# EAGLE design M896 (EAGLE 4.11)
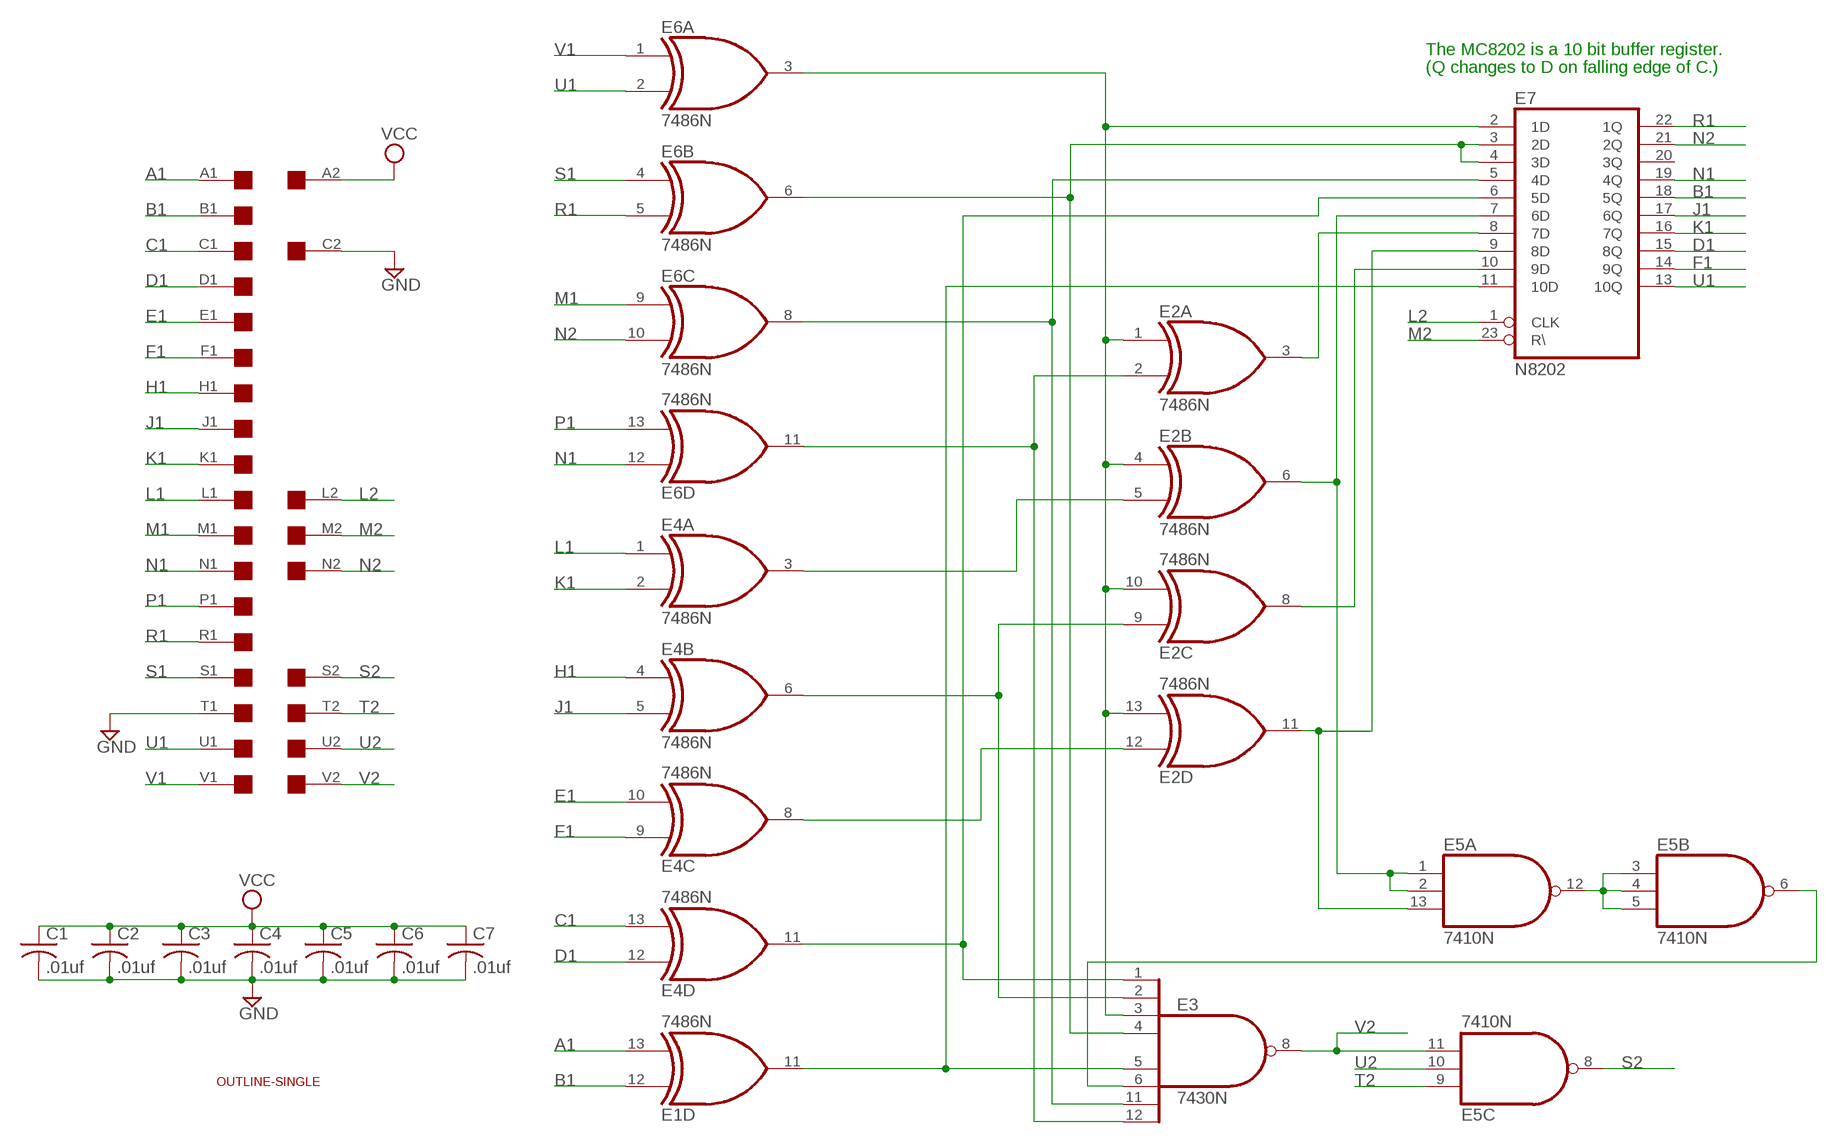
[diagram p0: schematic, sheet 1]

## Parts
C1  .01uf  C-US050-025X075  [C050-025X075]
C2  .01uf  C-US050-025X075  [C050-025X075]
C3  .01uf  C-US050-025X075  [C050-025X075]
C4  .01uf  C-US050-025X075  [C050-025X075]
C5  .01uf  C-US050-025X075  [C050-025X075]
C6  .01uf  C-US050-025X075  [C050-025X075]
C7  .01uf  C-US050-025X075  [C050-025X075]
E1  7486N  [DIL14]
E2  7486N  [DIL14]
E3  7430N  [DIL14]
E4  7486N  [DIL14]
E5  7410N  [DIL14]
E6  7486N  [DIL14]
E7  N8202  [DIL24]
U$1  EDGE-2CONNECTOR  [EDGE-CON2]
U$4  OUTLINE-SINGLE  [SINGLE]

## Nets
A1: E1.13(D:I1) U$1.A1
B1: E1.12(D:I0) E7.18(5Q) U$1.B1
C1: E4.13(D:I1) U$1.C1
D1: E4.12(D:I0) E7.15(8Q) U$1.D1
E1: E4.10(C:I1) U$1.E1
F1: E4.9(C:I0) E7.14(9Q) U$1.F1
GND [power]: C1.2 C2.2 C3.2 C4.2 C5.2 C6.2 C7.2 U$1.C2 U$1.T1
H1: E4.4(B:I0) U$1.H1
J1: E4.5(B:I1) E7.17(6Q) U$1.J1
K1: E4.2(A:I1) E7.16(7Q) U$1.K1
L1: E4.1(A:I0) U$1.L1
L2: E7.1(CLK) U$1.L2
M1: E6.9(C:I0) U$1.M1
M2: E7.23(R\) U$1.M2
N1: E6.12(D:I0) E7.19(4Q) U$1.N1
N2: E6.10(C:I1) E7.21(2Q) U$1.N2
N$1: E2.1(A:I0) E2.4(B:I0) E2.10(C:I1) E2.13(D:I1) E3.3(I2) E6.3(A:O) E7.2(1D)
N$2: E2.2(A:I1) E3.12(I7) E6.11(D:O)
N$3: E2.5(B:I1) E4.3(A:O)
N$4: E2.9(C:I0) E3.2(I1) E4.6(B:O)
N$5: E2.12(D:I0) E4.8(C:O)
N$6: E1.11(D:O) E3.5(I4) E7.11(10D)
N$7: E3.1(I0) E4.11(D:O) E7.6(5D)
N$8: E5.3(B:I0) E5.4(B:I1) E5.5(B:I2) E5.12(A:O)
N$9: E3.11(I6) E6.8(C:O) E7.5(4D)
N$10: E3.4(I3) E6.6(B:O) E7.3(2D) E7.4(3D)
N$11: E3.6(I5) E5.6(B:O)
N$12: E2.6(B:O) E5.1(A:I0) E5.2(A:I1) E7.7(6D)
N$13: E2.11(D:O) E5.13(A:I2) E7.9(8D)
N$14: E2.3(A:O) E7.8(7D)
N$15: E2.8(C:O) E7.10(9D)
P1: E6.13(D:I1) U$1.P1
R1: E6.5(B:I1) E7.22(1Q) U$1.R1
S1: E6.4(B:I0) U$1.S1
S2: E5.8(C:O) U$1.S2
T2: E5.9(C:I0) U$1.T2
U1: E6.2(A:I1) E7.13(10Q) U$1.U1
U2: E5.10(C:I1) U$1.U2
V1: E6.1(A:I0) U$1.V1
V2: E3.8(O) E5.11(C:I2) U$1.V2
VCC [power]: C1.1 C2.1 C3.1 C4.1 C5.1 C6.1 C7.1 U$1.A2
Unconnected: E1.1(A:I0) E1.2(A:I1) E1.3(A:O) E1.4(B:I0) E1.5(B:I1) E1.6(B:O) E1.8(C:O) E1.9(C:I0) E1.10(C:I1) E7.20(3Q) U$1.B2 U$1.D2 U$1.E2 U$1.F2 U$1.H2 U$1.J2 U$1.K2 U$1.P2 U$1.R2

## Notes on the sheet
- The MC8202 is a 10 bit buffer register.
- (Q changes to D on falling edge of C.)

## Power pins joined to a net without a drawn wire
GND: E1.7(P:GND) E2.7(P:GND) E3.7(GND) E4.7(P:GND) E5.7(P:GND) E6.7(P:GND) E7.12(GND)
VCC: E1.14(P:VCC) E2.14(P:VCC) E3.14(VCC) E4.14(P:VCC) E5.14(P:VCC) E6.14(P:VCC) E7.24(VCC)

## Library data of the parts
C1-C7 = rcl:C-US: CAPACITOR, American symbol
E1 E2 E4 E6 = 74xx-jameco:74*86: Quad 2-input EXCLUSIV-OR (XOR) gate
E3 = 74xx-jameco:74*30: 8-input NAND gate
E5 = 74xx-jameco:74*10: Triple 3-input NAND gate
E7 = dec-con:N8202: 10 bit register
U$1 = dec-con:EDGE-2: Double-Sided DEC edge connector.
U$4 = dec-con:OUTLINE-*: Board outlines for DEC boards.

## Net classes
1 power: width 0.508 mm

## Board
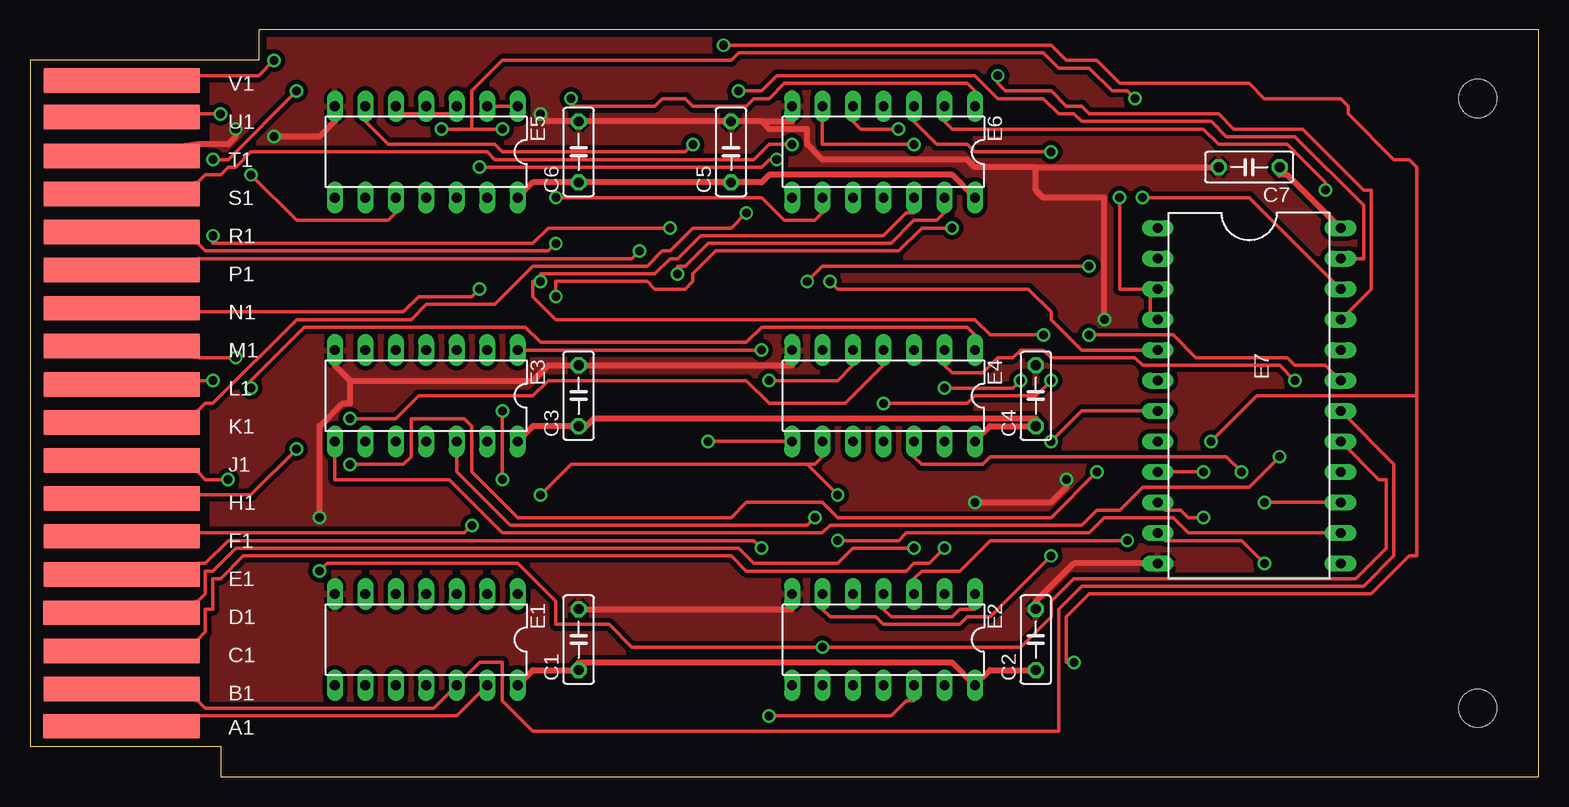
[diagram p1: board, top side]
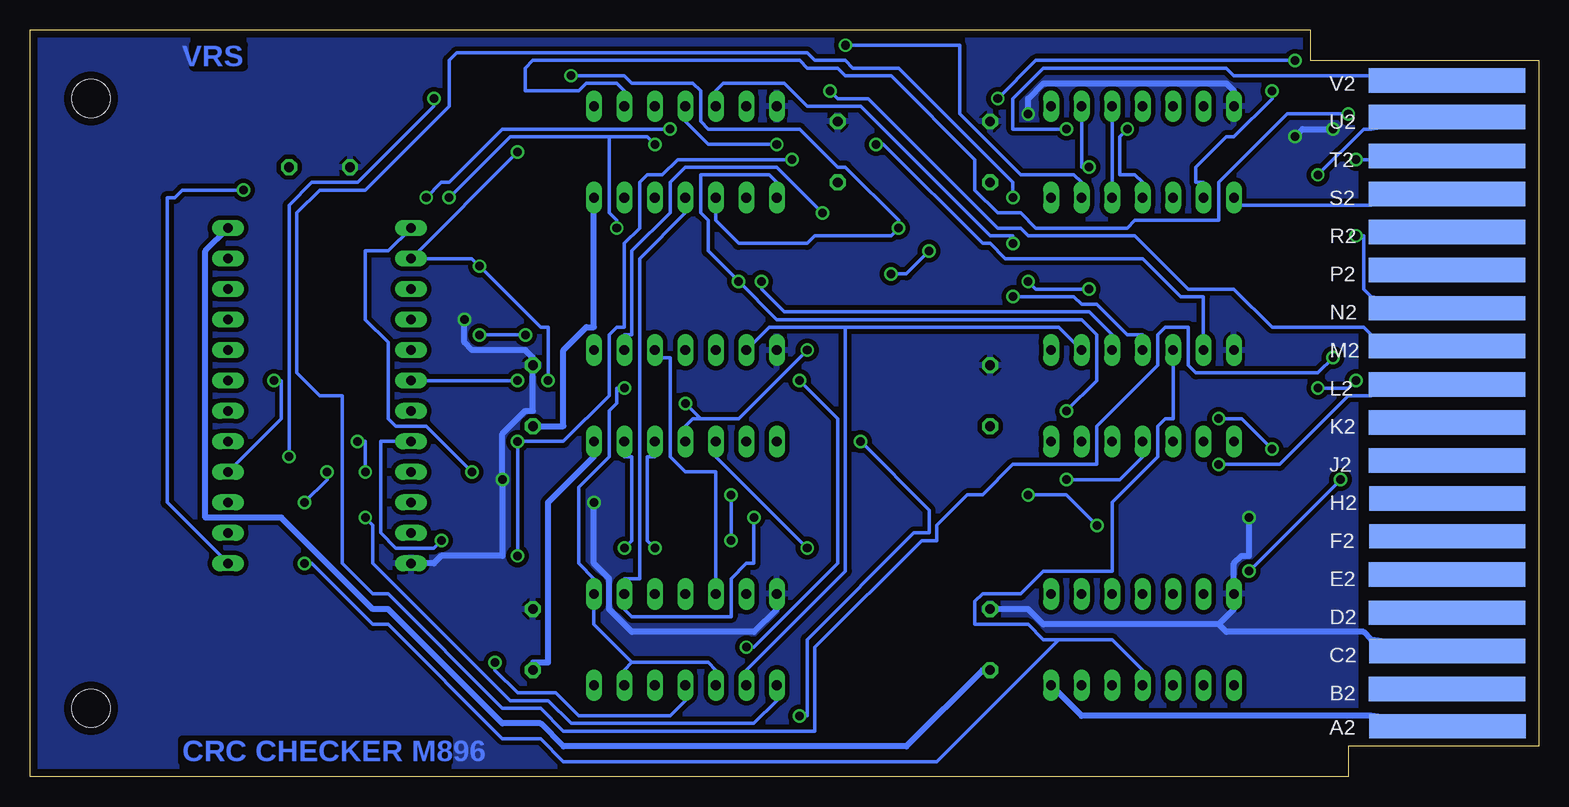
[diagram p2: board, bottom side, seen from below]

Size 125.73 x 62.23 mm. Coordinates in mm from the lower left corner, seen from the top.
Copper layers (1*16): Top 0.035mm / dielectric 1.5mm / Bottom 0.035mm
Design rules "10mils": minimum track width 12mil, minimum drill 28mil, track to track 10mil, track to pad 10mil, pad to pad 10mil, via to via 10mil, smd to smd 10mil, copper to edge 25mil, drill to drill 10mil, minimum pad ring 10mil, minimum via ring 8mil, stop-mask expansion 0mil, vias tented up to drill 0mil, thermal gap 10mil

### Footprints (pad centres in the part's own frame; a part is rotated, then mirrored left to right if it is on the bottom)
C050-025X075 = drill 0.813 octagon: 1 -2.54,0; 2 2.54,0
DIL14 = drill 0.813 long: 1 -7.62,-3.81; 2 -5.08,-3.81; 3 -2.54,-3.81; 4 0,-3.81; 5 2.54,-3.81; 6 5.08,-3.81; 7 7.62,-3.81; 8 7.62,3.81; 9 5.08,3.81; 10 2.54,3.81; 11 0,3.81; 12 -2.54,3.81; 13 -5.08,3.81; 14 -7.62,3.81
DIL24 = drill 0.813 long: 1 -12.7,-7.62; 2 -10.16,-7.62; 3 -7.62,-7.62; 4 -5.08,-7.62; 5 -2.54,-7.62; 6 0,-7.62; 7 2.54,-7.62; 8 5.08,-7.62; 9 7.62,-7.62; 10 10.16,-7.62; 11 12.7,-7.62; 12 15.24,-7.62; 13 15.24,7.62; 14 12.7,7.62; 15 10.16,7.62; 16 7.62,7.62; 17 5.08,7.62; 18 2.54,7.62; 19 0,7.62; 20 -2.54,7.62; 21 -5.08,7.62; 22 -7.62,7.62; 23 -10.16,7.62; 24 -12.7,7.62
EDGE-CON2 = smd 13.017 x 2.032: A1 7.633,4.207; B1 7.639,7.327; C1 7.636,10.489; D1 7.633,13.665; E1 7.642,16.84; F1 7.642,20.041; H1 7.642,23.19; J1 7.642,26.34; K1 7.642,29.515; L1 7.642,32.69; M1 7.642,35.89; N1 7.642,39.04; P1 7.642,42.24; R1 7.642,45.39; S1 7.642,48.565; T1 7.642,51.74; U1 7.642,54.966; V1 7.642,58.026 | smd 13.017 x 2.032 bottom: A2 7.614,4.207; B2 7.642,7.328; C2 7.617,10.49; D2 7.642,13.665; E2 7.642,16.84; F2 7.617,20.041; H2 7.617,23.19; J2 7.642,26.34; K2 7.642,29.515; L2 7.642,32.69; M2 7.642,35.89; N2 7.642,39.04; P2 7.642,42.24; R2 7.642,45.39; S2 7.642,48.565; T2 7.642,51.74; U2 7.642,54.966; V2 7.642,58.026
SINGLE = hole 3.175: 120.65,56.515; 120.65,5.715

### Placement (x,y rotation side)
C1  45.72,11.43 90 top
C2  83.82,11.43 90 top
C3  45.72,31.75 90 top
C4  83.82,31.75 90 top
C5  58.42,52.07 90 top
C6  45.72,52.07 90 top
C7  101.6,50.8 180 top
E1  33.02,11.43 180 top
E2  71.12,11.43 180 top
E3  33.02,31.75 180 top
E4  71.12,31.75 180 top
E5  33.02,52.07 180 top
E6  71.12,52.07 180 top
E7  101.6,33.02 270 top
U$1  0,0 0 top
U$4  0,0 0 top

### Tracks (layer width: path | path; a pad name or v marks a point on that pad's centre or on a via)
A1
  Top 0.305: E1.13 35.56,5.08 13.97,5.08 U$1.A1
B1
  Top 0.305: U$1.B1 13.97,6.35 14.61,5.71 33.66,5.71 E1.12 37.47,9.53 39.37,9.53 39.37,6.35 41.91,3.81 85.73,3.81 85.73,13.97 87.63,15.88 111.13,15.88 113.67,18.41 113.67,26.04 E7.18
C1  (via drill 0.71)
  Top 0.305: v76.2,19.05 74.93,17.78 73.66,17.78 73.03,17.14 59.69,17.14 58.42,18.41 17.78,18.41 15.88,16.51 15.24,16.51 15.24,13.97 14.61,13.97 14.61,12.06 13.97,11.43 U$1.C1
  Bottom 0.305: v76.2,19.05 75.57,19.68 75.57,26.67 76.2,26.67 E4.13
D1  (via drill 0.71)
  Top 0.305: v73.66,19.05 68.58,19.05 67.31,17.78 60.33,17.78 59.06,19.05 17.15,19.05 15.24,17.14 14.61,17.14 14.61,15.24 13.97,14.61 U$1.D1 | v100.97,25.4 99.7,26.67 80.01,26.67 79.38,26.04 74.3,26.04 73.66,26.67 E4.12 | v102.87,22.86 E7.15
  Bottom 0.305: v73.66,19.05 74.3,19.68 74.3,26.67 73.66,26.67 E4.12 | v102.87,22.86 100.97,24.77 v100.97,25.4
E1  (via drill 0.71)
  Top 0.305: v60.96,19.05 60.33,19.68 16.51,19.68 14.61,17.78 13.97,17.78 U$1.E1
  Bottom 0.305: v60.96,19.05 68.58,26.67 E4.10
F1  (via drill 0.71)
  Top 0.305: v36.83,20.95 36.2,20.32 13.97,20.32 U$1.F1 | v42.55,23.5 45.09,26.04 64.77,26.04 | 64.77,26.04 65.41,26.04 66.04,26.67 E4.9 | v67.31,19.68 72.39,19.68 73.03,20.32 88.27,20.32 89.54,21.59 95.25,21.59 96.52,20.32 E7.14 | 64.77,26.04 v67.31,23.5
  Bottom 0.305: v36.83,20.95 39.37,23.5 v42.55,23.5 | v67.31,23.5 v67.31,19.68
GND  (via drill 0.71)
  Top 0.508: E4.7 63.5,34.29 C3.2 43.18,34.29 41.91,33.02 26.67,33.02 | 26.67,33.02 25.4,34.29 E3.7 | E2.7 63.5,13.97 C1.2 | 26.67,33.02 26.67,31.11 26.04,31.11 24.13,29.21 v24.13,21.59 | v17.15,53.98 17.15,53.34 16.51,52.7 13.97,52.7 U$1.T1 | v20.32,53.34 24.13,53.34 25.4,54.61 E5.7 | C2.2 83.82,14.61 87,17.78 E7.12 | 60.96,54.61 63.5,54.61 E6.7 | 60.96,54.61 C5.2 C6.2 43.18,54.61 v42.55,55.24 | 83.82,50.8 78.74,50.8 78.11,51.44 66.04,51.44 64.77,52.7 64.77,53.98 61.6,53.98 60.96,54.61 | 83.82,50.8 C7.2 | v89.54,38.1 89.54,48.26 84.46,48.26 83.82,48.9 83.82,50.8 | v78.74,22.86 85.09,22.86 86.36,24.13 v86.36,24.77
  Bottom 0.508: 26.67,12.7 25.4,13.97 E1.7 25.4,17.78 24.77,18.41 24.13,18.41 v24.13,21.59 | 26.67,12.7 41.28,12.7 42.55,13.97 C1.2 | 26.67,12.7 26.04,12.06 14.61,12.06 13.97,11.43 U$1.C2 | v17.15,53.98 19.69,53.98 v20.32,53.34 | E7.12 92.08,17.78 91.44,18.41 86.36,18.41 v86.36,24.77 86.36,28.57 84.46,30.48 83.82,30.48 C4.2 83.82,34.92 84.46,35.56 88.9,35.56 89.54,36.2 v89.54,38.1 | v42.55,55.24 42.55,56.52 41.28,57.78 26.04,57.78 25.4,57.15 E5.7 | v78.74,22.86 78.74,17.78 77.47,16.51 77.47,13.97 75.57,12.06 65.41,12.06 63.5,13.97 E2.7
  pour Top (isolate 0.381): 15.24,62.23 125.73,62.23 125.73,0 15.24,0
  pour Bottom (isolate 0.381): 15.24,62.23 125.73,62.23 125.73,0 15.24,0
H1  (via drill 0.71)
  Top 0.305: v22.23,27.3 18.42,23.5 13.97,23.5 U$1.H1 | v26.67,29.84 30.48,29.84 32.39,31.75 41.91,31.75 43.18,33.02 59.69,33.02 61.6,31.11 67.95,31.11 71.12,34.29 E4.4
  Bottom 0.305: v22.23,27.3 24.77,29.84 v26.67,29.84
J1  (via drill 0.71)
  Top 0.305: v16.51,24.77 14.61,24.77 13.97,25.4 U$1.J1 | v24.13,17.14 24.77,17.78 40.64,17.78 43.82,14.61 43.82,12.7 48.26,12.7 50.17,10.79 v66.04,10.79 82.55,10.79 85.09,13.34 85.09,14.61 87,16.51 110.49,16.51 113.03,19.05 113.03,24.77 112.4,24.77 E7.17 | v61.6,33.02 67.31,33.02 68.58,34.29 E4.5
  Bottom 0.305: v16.51,24.77 v24.13,17.14 | v61.6,33.02 58.42,29.84 58.42,17.78 65.41,10.79 v66.04,10.79
K1  (via drill 0.71)
  Top 0.305: v59.69,46.99 58.42,45.72 55.25,45.72 53.34,43.81 52.71,43.81 51.44,42.55 41.91,42.55 38.74,39.37 33.02,39.37 31.75,38.1 22.23,38.1 15.24,31.11 14.61,31.11 13.97,30.48 U$1.K1 | v105.41,33.02 104.14,34.29 92.71,34.29 92.08,34.92 85.09,34.92 84.46,35.56 82.55,35.56 81.92,34.92 80.65,34.92 79.38,33.66 76.84,33.66 76.2,34.29 E4.2
  Bottom 0.305: v59.69,46.99 63.5,50.8 71.12,50.8 72.39,49.53 72.39,46.99 75.57,43.81 75.57,36.83 76.2,36.83 E4.2 | v105.41,33.02 104.78,33.02 104.78,29.84 E7.16
L1  (via drill 0.71)
  Top 0.305: v15.24,33.02 13.97,33.02 U$1.L1 | v18.42,32.38 18.42,33.02 22.86,37.47 41.28,37.47 42.55,36.2 59.69,36.2 60.96,37.47 78.11,37.47 78.74,36.83 E4.1
  Bottom 0.305: v15.24,33.02 15.88,32.38 v18.42,32.38
L2  (via drill 0.71)
  Top 0.305: v26.67,26.04 31.12,26.04 31.75,26.67 31.75,29.84 36.2,29.84 36.83,29.21 36.83,25.4 40.64,21.59 58.42,21.59 59.69,22.86 66.04,22.86 67.31,21.59 85.09,21.59 v88.9,25.4
  Bottom 0.305: v26.67,26.04 21.59,26.04 15.88,31.75 13.97,31.75 U$1.L2 | v88.9,25.4 92.71,29.21 95.25,29.21 95.89,29.84 95.89,36.2 97.79,38.1 97.79,43.81 95.89,43.81 E7.1
M1  (via drill 0.71)
  Top 0.305: v17.15,34.92 13.97,34.92 U$1.M1 | v43.82,48.26 60.96,48.26 62.87,46.35 65.41,46.35 66.04,46.99 E6.9
  Bottom 0.305: v17.15,34.92 18.42,33.66 28.58,33.66 29.21,34.29 29.21,37.47 31.12,37.47 31.75,36.83 31.75,34.29 36.83,29.21 36.83,26.04 43.82,26.04 46.36,23.5 47.63,23.5 50.17,20.95 50.17,19.68 51.44,19.68 60.33,10.79 60.33,3.81 81.28,3.81 83.19,5.71 86.36,5.71 95.89,15.24 97.16,15.24 99.7,17.78 99.7,31.75 101.6,31.75 103.51,33.66 103.51,46.99 101.6,48.9 97.79,48.9 90.81,55.88 90.81,59.69 90.17,60.33 60.96,60.33 60.33,59.69 57.79,59.69 57.15,59.05 53.34,59.05 43.82,49.53 v43.82,48.26
M2  (via drill 0.71)
  Top 0.305: v59.06,57.15 60.96,57.15 62.23,58.42 78.74,58.42 80.65,56.52 84.46,56.52 85.73,55.24 87,55.24 87.63,54.61 98.43,54.61 99.7,53.34 105.41,53.34 111.13,47.62 111.13,43.18 E7.23
  Bottom 0.305: v59.06,57.15 58.42,56.52 55.88,56.52 45.09,45.72 43.18,45.72 42.55,45.09 33.66,45.09 29.21,40.64 25.4,40.64 22.23,37.47 14.61,37.47 13.97,36.83 U$1.M2
N1  (via drill 0.71)
  Top 0.305: v37.47,40.64 36.83,40.01 32.39,40.01 31.12,38.73 13.97,38.73 U$1.N1 | E6.12 73.66,46.99 73.03,46.99 71.12,45.09 55.88,45.09 53.98,43.18 53.34,43.18 52.07,41.91 42.55,41.91 v42.55,41.27 41.91,41.27 41.91,40.01 43.82,38.1 78.74,38.1 80.01,36.83 v84.46,36.83 | v88.27,36.83 95.25,36.83 97.16,34.92 104.78,34.92 105.41,34.29 107.95,34.29 E7.19
  Bottom 0.305: v37.47,40.64 41.91,40.64 v42.55,41.27 | v84.46,36.83 v88.27,36.83
N2  (via drill 0.71)
  Top 0.305: v15.24,45.09 15.24,44.45 41.91,44.45 43.18,45.72 v53.34,45.72 | v80.65,58.42 80.65,57.78 81.28,57.15 85.09,57.15 86.36,55.88 87.63,55.88 88.27,55.24 99.06,55.24 100.33,53.98 106.05,53.98 111.13,48.9 111.76,48.9 111.76,40.64 E7.21
  Bottom 0.305: v15.24,45.09 14.61,45.09 14.61,40.64 13.97,40.01 U$1.N2 | E6.10 68.58,46.35 66.68,44.45 60.96,44.45 60.33,45.09 53.98,45.09 v53.34,45.72 53.34,46.35 57.79,50.8 58.42,50.8 61.6,53.98 69.22,53.98 69.85,54.61 69.85,57.15 70.49,57.78 75.57,57.78 76.2,58.42 v80.65,58.42
N$1  (via drill 0.71)
  Top 0.305: E2.4 71.12,13.97 71.76,13.34 76.84,13.34 77.47,13.97 78.74,13.97 E2.1 | v85.09,52.07 78.74,52.07 78.11,52.7 75.57,52.7 73.66,54.61 E6.3 | v64.77,41.27 66.04,42.55 v88.27,42.55 | v76.2,32.38 81.92,32.38 v82.55,33.02
  Bottom 0.305: 75.57,9.53 69.22,9.53 68.58,8.89 E2.10 | 75.57,9.53 76.2,8.89 E2.13 | 75.57,9.53 78.74,12.7 E2.1 78.74,16.51 80.01,17.78 80.01,24.13 77.47,26.67 77.47,30.48 76.84,31.11 76.84,32.38 v76.2,32.38 | v85.09,52.07 E7.2 88.9,43.18 v88.27,42.55 83.19,37.47 82.55,37.47 v82.55,33.02 | v64.77,41.27 64.77,40.64 62.87,38.73 37.47,38.73 35.56,36.83 E3.3
N$2  (via drill 0.71)
  Top 0.305: v65.41,21.59 64.77,20.95 40.01,20.95 35.56,25.4 E3.12
  Bottom 0.305: E6.11 71.12,46.99 74.93,43.18 74.93,16.51 76.2,16.51 E2.2 76.2,13.97 75.57,13.34 67.31,13.34 67.31,16.51 66.04,17.78 65.41,17.78 v65.41,21.59
N$3
  Bottom 0.305: E2.5 68.58,25.4 71.12,25.4 72.39,26.67 72.39,34.92 73.03,34.92 E4.3
N$4
  Bottom 0.305: 57.79,37.47 57.79,17.14 66.04,8.89 E2.9 | 57.79,37.47 64.14,37.47 E4.6 | 57.79,37.47 40.01,37.47 E3.2
N$5  (via drill 0.71)
  Top 0.305: v61.6,5.08 71.76,5.08 73.03,6.35 73.66,6.35 E2.12 | v56.52,27.94 E4.8
  Bottom 0.305: v56.52,27.94 50.8,22.23 50.8,20.32 52.07,20.32 60.96,11.43 60.96,5.08 v61.6,5.08
N$6  (via drill 0.71)
  Top 0.305: v102.87,17.78 100.97,19.68 94.62,19.68 E7.11
  Bottom 0.305: 40.01,11.43 35.56,11.43 33.02,8.89 E1.11 | 40.01,11.43 41.28,11.43 42.55,12.7 46.99,12.7 46.99,14.61 46.36,15.24 43.18,15.24 41.28,17.14 35.56,17.14 35.56,22.86 31.75,26.67 31.75,29.21 31.12,29.84 30.48,29.84 E3.5 | v102.87,17.78 102.24,17.78 97.16,12.7 95.89,12.7 86.36,3.17 83.19,3.17 81.28,1.27 50.17,1.27 40.01,11.43
N$7  (via drill 0.71)
  Top 0.305: E3.1 v60.96,35.56 | v85.09,33.02 83.82,31.75 78.74,31.75 78.11,31.11 v71.12,31.11
  Bottom 0.305: v60.96,35.56 66.68,29.84 69.85,29.84 | 69.85,29.84 70.49,29.84 71.12,29.21 E4.11 | 69.85,29.84 v71.12,31.11 | v85.09,33.02 E7.6
N$8
  Top 0.305: E5.5 31.12,55.24 32.39,55.24 E5.4 33.66,55.24 34.93,55.24 E5.3
  Bottom 0.305: E5.12 E5.3
N$9  (via drill 0.71)
  Top 0.305: v39.37,24.77 v39.37,30.48 | v66.68,41.27 67.31,40.64 83.19,40.64 85.09,38.73 85.09,38.1 87.63,35.56 E7.5
  Bottom 0.305: v39.37,24.77 34.93,24.77 33.02,26.67 E3.11 | v39.37,30.48 36.83,33.02 36.83,36.83 38.1,38.1 63.5,38.1 v66.68,41.27 69.22,43.81 69.22,46.35 69.85,46.99 69.85,50.16 64.14,50.16 63.5,49.53 E6.8
N$10  (via drill 0.71)
  Top 0.305: v73.66,52.7 66.04,52.7 E6.6 | v90.81,48.26 90.81,40.64 E7.3 93.35,40.01 93.35,38.73 E7.4 | v43.82,40.01 43.82,41.27 51.44,41.27 52.07,40.64 54.61,40.64 55.25,41.27 55.25,41.91 57.15,43.81 72.39,43.81 74.3,45.72 v76.84,45.72
  Bottom 0.305: v73.66,52.7 74.3,53.34 77.47,53.34 | 77.47,53.34 85.73,53.34 v90.81,48.26 | v43.82,40.01 38.74,40.01 38.1,39.37 36.83,39.37 34.29,36.83 33.02,36.83 E3.4 | v76.84,45.72 76.84,46.35 77.47,46.99 77.47,53.34
N$11  (via drill 0.71)
  Top 0.305: v55.25,52.7 54.61,52.07 39.37,52.07 38.74,52.7 29.85,52.7 27.94,54.61 E5.6
  Bottom 0.305: v55.25,52.7 54.61,52.7 46.36,44.45 45.72,44.45 44.45,43.18 33.02,43.18 29.85,40.01 27.94,40.01 E3.6
N$12  (via drill 0.71)
  Top 0.305: E5.2 E5.1 | v85.09,27.94 87.63,30.48 E7.7 | v85.09,18.41 80.01,13.34 78.11,13.34 77.47,12.7 71.12,12.7 70.49,13.34 66.68,13.34 66.04,13.97 E2.6 | v37.47,50.8 60.96,50.8 61.6,51.44 v62.23,51.44
  Bottom 0.305: v85.09,18.41 v85.09,27.94 81.28,27.94 77.47,31.75 77.47,36.83 76.84,37.47 76.2,37.47 76.2,44.45 74.93,45.72 74.93,49.53 74.3,50.16 73.03,50.16 71.76,51.44 v62.23,51.44 | v37.47,50.8 38.1,50.8 E5.2
N$13  (via drill 0.71)
  Top 0.305: v57.79,60.96 85.09,60.96 86.36,59.69 88.9,59.69 90.81,57.78 101.6,57.78 102.87,56.52 109.22,56.52 109.86,55.88 109.86,55.24 113.67,51.44 114.94,51.44 115.57,50.8 115.57,31.75 | 115.57,31.75 115.57,18.41 114.94,18.41 111.76,15.24 88.27,15.24 86.36,13.34 86.36,9.53 v87,9.53 | v98.43,27.94 102.24,31.75 115.57,31.75 | v97.79,25.4 E7.9
  Bottom 0.305: v57.79,60.96 48.26,60.96 48.26,55.24 43.18,50.16 38.74,50.16 38.1,49.53 E5.13 | v87,9.53 87,8.89 85.09,6.99 81.92,6.99 80.01,5.08 72.39,5.08 71.12,6.35 E2.11 | v97.79,25.4 97.79,27.94 v98.43,27.94
N$14  (via drill 0.71)
  Top 0.305: v91.44,19.68 80.01,19.68 77.47,17.14 74.3,17.14 73.66,16.51 E2.3
  Bottom 0.305: v91.44,19.68 92.08,19.05 95.25,19.05 96.52,20.32 96.52,27.94 E7.8
N$15  (via drill 0.71)
  Top 0.305: v97.79,21.59 96.52,21.59 95.89,22.23 94.62,22.23 E7.10
  Bottom 0.305: v97.79,21.59 97.16,20.95 97.16,17.78 85.73,6.35 82.55,6.35 80.65,4.45 65.41,4.45 63.5,6.35 E2.8
P1  (via drill 0.71)
  Top 0.305: v50.8,43.81 50.17,43.18 13.97,43.18 U$1.P1 | v53.98,41.91 53.98,42.55 54.61,42.55 56.52,44.45 71.76,44.45 73.66,46.35 75.57,46.35 76.2,46.99 E6.13
  Bottom 0.305: v50.8,43.81 52.71,41.91 v53.98,41.91
R1  (via drill 0.71)
  Top 0.305: v43.82,44.45 43.18,43.81 14.61,43.81 13.97,44.45 U$1.R1 | v92.71,48.26 101.6,48.26 E7.22 | v72.39,53.98 69.22,53.98 68.58,54.61 E6.5
  Bottom 0.305: v43.82,44.45 43.82,45.09 45.72,45.09 56.52,55.88 60.96,55.88 62.87,57.78 67.95,57.78 68.58,57.15 E6.5 | v92.71,48.26 91.44,49.53 90.81,49.53 86.36,53.98 v72.39,53.98
S1  (via drill 0.71)
  Top 0.305: v63.5,52.7 61.6,52.7 60.33,51.44 38.74,51.44 38.1,52.07 18.42,52.07 17.15,50.8 16.51,50.8 15.88,50.16 14.61,50.16 13.97,49.53 U$1.S1
  Bottom 0.305: v63.5,52.7 69.22,52.7 71.12,54.61 E6.4
S2
  Bottom 0.305: E5.8 24.77,47.62 13.97,47.62 U$1.S2
T2  (via drill 0.71)
  Top 0.305: v15.24,51.44 16.51,51.44 v22.23,57.15
  Bottom 0.305: v15.24,51.44 13.97,51.44 U$1.T2 | v22.23,57.15 22.23,56.52 25.4,53.34 26.04,53.34 28.58,50.8 28.58,49.53 27.94,49.53 E5.9
U1  (via drill 0.71)
  Top 0.305: v15.88,55.24 13.97,55.24 U$1.U1 | v107.95,48.9 107.95,49.53 104.78,52.7 99.06,52.7 97.79,53.98 76.84,53.98 76.2,54.61 E6.2
  Bottom 0.305: v15.88,55.24 20.96,55.24 26.67,49.53 26.67,46.35 33.66,46.35 34.29,45.72 41.91,45.72 43.18,46.99 45.09,46.99 46.99,48.9 46.99,51.44 53.98,58.42 57.79,58.42 58.42,59.05 60.96,59.05 61.6,59.69 83.82,59.69 84.46,59.05 84.46,57.15 80.01,57.15 79.38,57.78 76.84,57.78 76.2,57.15 E6.2 | v107.95,48.9 113.03,48.9 113.67,48.26 114.3,48.26 114.3,22.86 E7.13
U2  (via drill 0.71)
  Top 0.305: v18.42,50.16 22.23,46.35 29.85,46.35 30.48,46.99 E5.10
  Bottom 0.305: v18.42,50.16 14.61,53.98 13.97,53.98 U$1.U2
V1  (via drill 0.71)
  Top 0.305: v20.32,59.69 19.05,58.42 13.97,58.42 U$1.V1 | v45.09,56.52 45.09,55.88 52.07,55.88 52.71,56.52 54.61,56.52 55.25,55.88 59.69,55.88 60.33,56.52 61.6,56.52 62.87,57.78 78.11,57.78 78.74,57.15 E6.1
  Bottom 0.305: v20.32,59.69 41.91,59.69 v45.09,56.52
V2  (via drill 0.71)
  Top 0.305: 36.83,53.98 v34.29,53.98 | 36.83,53.98 v39.37,53.98 | v104.14,26.67 101.6,24.13 92.71,24.13 90.81,22.23 88.9,22.23 87.63,20.95 66.68,20.95 66.04,20.32 39.37,20.32 34.93,24.77 25.4,24.77 E3.8 | v92.08,56.52 91.44,57.15 90.17,57.15 88.27,59.05 85.73,59.05 84.46,60.33 59.06,60.33 58.42,59.69 39.37,59.69 36.83,57.15 36.83,53.98
  Bottom 0.305: v39.37,53.98 43.82,53.98 43.82,56.52 41.28,59.05 26.04,59.05 25.4,58.42 13.97,58.42 U$1.V2 | v34.29,53.98 34.93,53.34 34.93,50.16 33.66,50.16 33.02,49.53 E5.11 | v104.14,26.67 104.14,47.62 102.24,49.53 98.43,49.53 92.08,55.88 v92.08,56.52
VCC
  Top 0.508: E5.14 41.91,49.53 C6.1 C5.1 60.96,49.53 61.6,50.16 76.84,50.16 E6.14 | E3.14 41.91,29.21 C3.1 46.36,29.21 46.99,29.84 83.82,29.84 C4.1 80.01,29.21 E4.14 | E7.24 104.78,50.16 104.14,50.16 C7.1 | C2.1 80.01,8.89 E2.14 76.84,9.53 45.72,9.53 C1.1 41.91,8.89 E1.14
  Bottom 0.508: E6.14 78.74,37.47 79.38,37.47 81.28,35.56 81.28,29.21 C4.1 | E1.14 38.1,5.08 13.97,5.08 U$1.A2 | E7.24 111.13,43.81 111.13,21.59 104.78,21.59 97.16,13.97 95.89,13.97 86.36,4.45 83.19,4.45 81.28,2.54 52.71,2.54 46.36,8.89 C1.1 | E4.14 78.74,26.67 82.55,22.86 82.55,9.53 83.82,9.53 C2.1

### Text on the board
Bottom: VRS | CRC CHECKER M896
